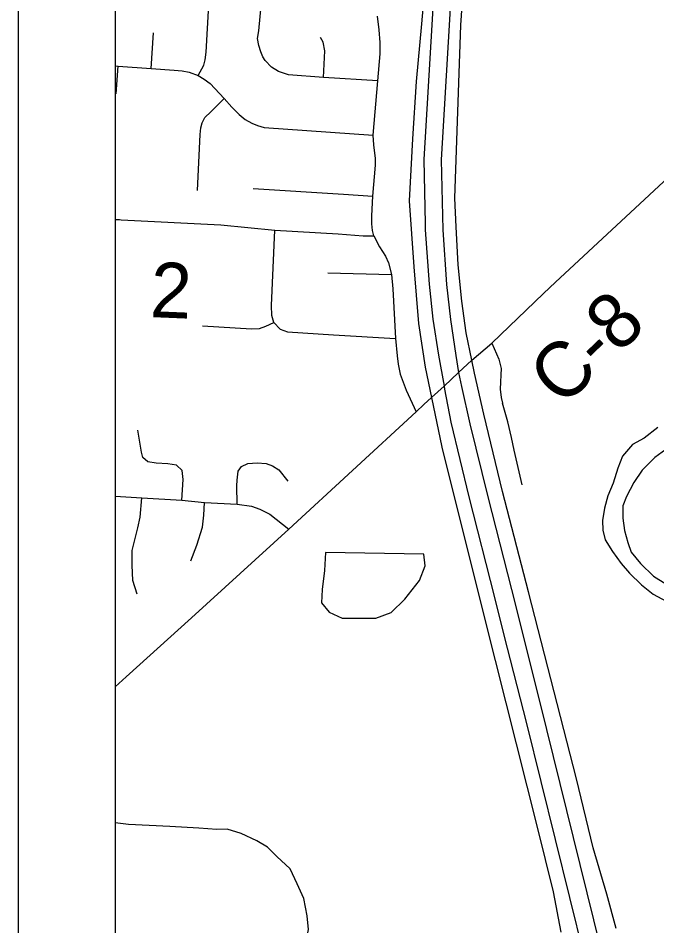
# Model space of a CAD drawing. Extents: x 208586767.6 to 208586821.4, y -134301046.9 to -134301022.9.
# Drawn here: x 208586777.928 to 208586778.586, y -134301026.633 to -134301025.698 of the extents above; entities that cross this region are included whole.
import ezdxf

# ---------------------------------------------------------------- set-up
doc = ezdxf.new("R2010")
doc.units = 0
for name, color, linetype in [('GM_X_City_Street', 7, 'Continuous'), ('GM_X_Corporation', 7, 'Continuous'), ('GM_X_County_Road', 7, 'Continuous'), ('GM_X_County_Road_Text', 7, 'Continuous'), ('GM_X_Interchange_Ramps', 7, 'Continuous'), ('GM_X_Interstate_Route', 7, 'Continuous'), ('GM_X_Major_River', 7, 'Continuous'), ('GM_X_Minor_Lake', 7, 'Continuous'), ('GM_X_Township_Road', 7, 'Continuous'), ('GM_X_Township_Road_Text', 7, 'Continuous'), ('SH_Data', 7, 'Continuous')]:
    doc.layers.add(name, color=color, linetype=linetype)

msp = doc.modelspace()

# ---------------------------------------------------------------- linework, layer by layer
at = {"layer": 'GM_X_City_Street'}
for p, q in [((208586778.06535, -134301025.74994), (208586778.06782, -134301025.71349)), ((208586778.02929, -134301025.77634), (208586778.03123, -134301025.74774)), ((208586778.24723, -134301025.96052), (208586778.31285, -134301025.96247))]:
    msp.add_line(p, q, dxfattribs=at)
for points in [[(208586778.2989, -134301025.76283), (208586778.24288, -134301025.75925), (208586778.20661, -134301025.7567), (208586778.19657, -134301025.7533), (208586778.18925, -134301025.7487), (208586778.18278, -134301025.74189), (208586778.18022, -134301025.73797), (208586778.17818, -134301025.73287), (208586778.17614, -134301025.72656), (208586778.17491, -134301025.7193), (208586778.17614, -134301025.71124), (208586778.18055, -134301025.6633)], [(208586778.11369, -134301025.75735), (208586778.1194, -134301025.74654), (208586778.12079, -134301025.74129), (208586778.12203, -134301025.73311), (208586778.1245, -134301025.68461), (208586778.12311, -134301025.67658), (208586778.12109, -134301025.67132)], [(208586778.2945, -134301025.92264), (208586778.2933, -134301025.91708), (208586778.29241, -134301025.91011), (208586778.29241, -134301025.90191), (208586778.29361, -134301025.88147), (208586778.2963, -134301025.84984), (208586778.2963, -134301025.84268), (208586778.2945, -134301025.82866), (208586778.2939, -134301025.81881), (208586778.2989, -134301025.76283), (208586778.30129, -134301025.73508), (208586778.30129, -134301025.72333), (208586778.30026, -134301025.71022), (208586778.29856, -134301025.69609)], [(208586778.24288, -134301025.75925), (208586778.24424, -134301025.73184), (208586778.24254, -134301025.72299), (208586778.23982, -134301025.71805)], [(208586778.02826, -134301025.74752), (208586778.03123, -134301025.74774), (208586778.06535, -134301025.74994), (208586778.08913, -134301025.75179), (208586778.09732, -134301025.75241), (208586778.10458, -134301025.75395), (208586778.11369, -134301025.75735), (208586778.11986, -134301025.76121), (208586778.1262, -134301025.76554), (208586778.14063, -134301025.78102), (208586778.14837, -134301025.78998), (208586778.1559, -134301025.79751), (208586778.16221, -134301025.8026), (208586778.16913, -134301025.80646), (208586778.17483, -134301025.80891), (208586778.18175, -134301025.81094), (208586778.2939, -134301025.81881)], [(208586778.11297, -134301025.87573), (208586778.11588, -134301025.81814), (208586778.11657, -134301025.8113), (208586778.11776, -134301025.80601), (208586778.12067, -134301025.80053), (208586778.12664, -134301025.7949), (208586778.14063, -134301025.78102)], [(208586778.17038, -134301025.87371), (208586778.26348, -134301025.87968), (208586778.29361, -134301025.88147)], [(208586778.19163, -134301026.01177), (208586778.18946, -134301026.00447), (208586778.18907, -134301025.9942), (208586778.19268, -134301025.91668)], [(208586778.11803, -134301026.01532), (208586778.16854, -134301026.01827), (208586778.17702, -134301026.01788), (208586778.18354, -134301026.01551), (208586778.19163, -134301026.01177)], [(208586778.19163, -134301026.01177), (208586778.19814, -134301026.01847), (208586778.20564, -134301026.02144), (208586778.2532, -134301026.02439), (208586778.31711, -134301026.02828)], [(208586778.44743, -134301026.1789), (208586778.43917, -134301026.14342), (208586778.43638, -134301026.13027), (208586778.4326, -134301026.11416), (208586778.4273, -134301026.09493)], [(208586778.09676, -134301026.19487), (208586778.09817, -134301026.17337), (208586778.09723, -134301026.16426), (208586778.09139, -134301026.15888), (208586778.08228, -134301026.15725), (208586778.07036, -134301026.15678), (208586778.06172, -134301026.15538), (208586778.05681, -134301026.15094), (208586778.05519, -134301026.14548), (208586778.05163, -134301026.12267)], [(208586778.15401, -134301026.19884), (208586778.15357, -134301026.17998), (208586778.15376, -134301026.17409), (208586778.1549, -134301026.16496), (208586778.15833, -134301026.16001), (208586778.16498, -134301026.15717), (208586778.17448, -134301026.1564), (208586778.18379, -134301026.15717), (208586778.19025, -134301026.15926), (208586778.1969, -134301026.16344), (208586778.20593, -134301026.1752)], [(208586778.02826, -134301026.19074), (208586778.05564, -134301026.19229), (208586778.09676, -134301026.19487), (208586778.12036, -134301026.1972), (208586778.15401, -134301026.19884), (208586778.16877, -134301026.20108), (208586778.17714, -134301026.20393), (208586778.1874, -134301026.20906), (208586778.20704, -134301026.2248)], [(208586778.05097, -134301026.29159), (208586778.04629, -134301026.27758), (208586778.04559, -134301026.26169), (208586778.04583, -134301026.24674), (208586778.05167, -134301026.22314), (208586778.05401, -134301026.21215), (208586778.05564, -134301026.19229)], [(208586778.10611, -134301026.25725), (208586778.11218, -134301026.24113), (208586778.11803, -134301026.22244), (208586778.11966, -134301026.21029), (208586778.12036, -134301026.1972)]]:
    msp.add_lwpolyline(points, dxfattribs=at)
at = {"layer": 'GM_X_Corporation'}
for points in [[(208586780.70516, -134301026.71709), (208586780.71564, -134301026.59783), (208586780.72517, -134301026.42102), (208586780.75163, -134301025.96027), (208586780.75793, -134301025.857), (208586780.78397, -134301025.42935), (208586780.79299, -134301025.29198), (208586780.79385, -134301025.27895), (208586780.84682, -134301024.47213), (208586780.8523, -134301024.30943), (208586780.86081, -134301024.16936), (208586780.86862, -134301024.04072), (208586778.02826, -134301024.04072), (208586778.02826, -134301026.87222)], [(208586778.02826, -134301025.18459), (208586778.02826, -134301030.32371)]]:
    msp.add_lwpolyline(points, dxfattribs=at)
at = {"layer": 'GM_X_County_Road'}
for points in [[(208586778.48186, -134301025.97017), (208586778.6751, -134301025.79061), (208586778.82536, -134301025.64512), (208586778.89868, -134301025.57327), (208586778.92318, -134301025.54795), (208586778.93255, -134301025.53677), (208586778.9411, -134301025.52543), (208586778.94685, -134301025.51639), (208586778.95162, -134301025.50817), (208586778.95606, -134301025.5006), (208586778.96214, -134301025.48926), (208586778.96807, -134301025.47479), (208586778.97201, -134301025.4618), (208586778.9748, -134301025.45358), (208586778.97503, -134301025.45268)], [(208586778.3462, -134301026.0964), (208586778.35402, -134301026.08917), (208586778.36693, -134301026.0774), (208586778.38197, -134301026.06338), (208586778.39572, -134301026.05057), (208586778.41616, -134301026.03294), (208586778.46932, -134301025.98182), (208586778.48186, -134301025.97017)], [(208586778.02826, -134301026.38702), (208586778.03951, -134301026.37671), (208586778.10675, -134301026.31605), (208586778.20704, -134301026.2248), (208586778.33839, -134301026.10364), (208586778.3462, -134301026.0964)], [(208586778.21779, -134301026.71457), (208586778.22241, -134301026.65984), (208586778.22738, -134301026.63719), (208586778.22601, -134301026.62311), (208586778.22261, -134301026.6052), (208586778.21579, -134301026.58985), (208586778.20829, -134301026.57449), (208586778.19464, -134301026.5617), (208586778.1851, -134301026.5521), (208586778.17418, -134301026.5457), (208586778.15781, -134301026.53803), (208586778.14348, -134301026.53355), (208586778.13275, -134301026.53413), (208586778.11428, -134301026.53272), (208586778.08461, -134301026.53085), (208586778.04209, -134301026.52875), (208586778.02826, -134301026.52725)]]:
    msp.add_lwpolyline(points, dxfattribs=at)
at = {"layer": 'GM_X_Interchange_Ramps'}
for points in [[(208586778.36431, -134301025.42027), (208586778.36128, -134301025.46232), (208586778.35774, -134301025.52026), (208586778.35293, -134301025.5982), (208586778.34382, -134301025.70396), (208586778.33826, -134301025.76342), (208586778.3344, -134301025.82239), (208586778.33117, -134301025.88639), (208586778.33582, -134301025.95432), (208586778.34072, -134301026.01294), (208586778.3475, -134301026.05774), (208586778.35402, -134301026.08917), (208586778.36452, -134301026.14002), (208586778.409, -134301026.31766), (208586778.46285, -134301026.53156), (208586778.4793, -134301026.59823), (208586778.48741, -134301026.6399)], [(208586778.54432, -134301026.63619), (208586778.53467, -134301026.60078), (208586778.52068, -134301026.55285), (208586778.50337, -134301026.48186), (208586778.45391, -134301026.28908), (208586778.42702, -134301026.18591), (208586778.40784, -134301026.1063), (208586778.39848, -134301026.06395), (208586778.39572, -134301026.05057), (208586778.38989, -134301026.02228), (208586778.38538, -134301025.98985), (208586778.38134, -134301025.95231), (208586778.37941, -134301025.91322), (208586778.37794, -134301025.88353), (208586778.38438, -134301025.70541), (208586778.39313, -134301025.57624), (208586778.39569, -134301025.48877)]]:
    msp.add_lwpolyline(points, dxfattribs=at)
at = {"layer": 'GM_X_Interstate_Route'}
for points in [[(208586778.39952, -134301025.26386), (208586778.39796, -134301025.28965), (208586778.39344, -134301025.36115), (208586778.38905, -134301025.43479), (208586778.38269, -134301025.53173), (208586778.36405, -134301025.84428), (208586778.36558, -134301025.91644), (208586778.36953, -134301025.97258), (208586778.37348, -134301026.00877), (208586778.37918, -134301026.04562), (208586778.38197, -134301026.06338), (208586778.38493, -134301026.07769), (208586778.39364, -134301026.11629), (208586778.41206, -134301026.1913), (208586778.44057, -134301026.30293), (208586778.47259, -134301026.43102), (208586778.54836, -134301026.73847)], [(208586778.38117, -134301025.2688), (208586778.38071, -134301025.27724), (208586778.37544, -134301025.36086), (208586778.37106, -134301025.4345), (208586778.3647, -134301025.53144), (208586778.34605, -134301025.84398), (208586778.34746, -134301025.91013)], [(208586778.34746, -134301025.91013), (208586778.34759, -134301025.91614), (208586778.35154, -134301025.97229), (208586778.35548, -134301026.00848), (208586778.36119, -134301026.04533), (208586778.36693, -134301026.0774), (208586778.36748, -134301026.08032)], [(208586778.36748, -134301026.08032), (208586778.37391, -134301026.11441), (208586778.39233, -134301026.19118), (208586778.41887, -134301026.29514), (208586778.42869, -134301026.3339)], [(208586778.42869, -134301026.3339), (208586778.45177, -134301026.42498), (208586778.52575, -134301026.72358)]]:
    msp.add_lwpolyline(points, dxfattribs=at)
at = {"layer": 'GM_X_Major_River'}
for points in [[(208586778.58724, -134301026.12), (208586778.57315, -134301026.13095), (208586778.56098, -134301026.13735), (208586778.55068, -134301026.14946), (208586778.54607, -134301026.16197), (208586778.54106, -134301026.17713), (208586778.53568, -134301026.1904), (208586778.53221, -134301026.20291), (208586778.53024, -134301026.21582), (208586778.53057, -134301026.22569), (208586778.5328, -134301026.23557), (208586778.54032, -134301026.24776), (208586778.54937, -134301026.25996), (208586778.55804, -134301026.26987), (208586778.5705, -134301026.28208), (208586778.58221, -134301026.29163), (208586778.59583, -134301026.2989)], [(208586778.59547, -134301026.14245), (208586778.58405, -134301026.15075), (208586778.57109, -134301026.16398), (208586778.5623, -134301026.17647), (208586778.55502, -134301026.19087), (208586778.55118, -134301026.20072), (208586778.55112, -134301026.21325), (208586778.55295, -134301026.22617), (208586778.5563, -134301026.23834), (208586778.55967, -134301026.24823), (208586778.56947, -134301026.26005), (208586778.58268, -134301026.27302), (208586778.59554, -134301026.28105)]]:
    msp.add_lwpolyline(points, dxfattribs=at)
at = {"layer": 'GM_X_Minor_Lake'}
for points in [[(208586778.24476, -134301026.24853), (208586778.24382, -134301026.26712), (208586778.24135, -134301026.28684), (208586778.24083, -134301026.3005), (208586778.24871, -134301026.31007), (208586778.26193, -134301026.31628), (208586778.27863, -134301026.31644), (208586778.29684, -134301026.31625), (208586778.31246, -134301026.31033), (208586778.32664, -134301026.2968), (208586778.34163, -134301026.27759), (208586778.34747, -134301026.26246), (208586778.34607, -134301026.25029)], [(208586778.34607, -134301026.25029), (208586778.24476, -134301026.24853)]]:
    msp.add_lwpolyline(points, dxfattribs=at)
at = {"layer": 'GM_X_Township_Road'}
msp.add_line((208586778.02826, -134301025.90551), (208586778.03251, -134301025.90578), dxfattribs=at)
for points in [[(208586778.03251, -134301025.90578), (208586778.03451, -134301025.9059), (208586778.13716, -134301025.91121), (208586778.19268, -134301025.91668), (208586778.2578, -134301025.92026), (208586778.28361, -134301025.92235), (208586778.2945, -134301025.92264), (208586778.30047, -134301025.93368), (208586778.30674, -134301025.94338), (208586778.30972, -134301025.95024), (208586778.31285, -134301025.96247), (208586778.31416, -134301025.977), (208586778.31711, -134301026.02828), (208586778.3187, -134301026.0462), (208586778.3196, -134301026.05483), (208586778.32164, -134301026.06503), (208586778.32807, -134301026.0816), (208586778.33839, -134301026.10364)], [(208586778.41616, -134301026.03294), (208586778.42323, -134301026.04955), (208586778.42586, -134301026.05913), (208586778.42553, -134301026.06583), (208586778.42504, -134301026.07306), (208586778.42471, -134301026.08045), (208586778.42586, -134301026.089), (208586778.4273, -134301026.09493)]]:
    msp.add_lwpolyline(points, dxfattribs=at)
at = {"layer": 'SH_Data'}
for p, q in [((208586777.92826, -134301023.94072), (208586777.92826, -134301030.94072)), ((208586778.02826, -134301024.04072), (208586778.02826, -134301030.84072))]:
    msp.add_line(p, q, dxfattribs=at)

# ---------------------------------------------------------------- texts
at = {"layer": 'GM_X_County_Road_Text'}
msp.add_text('C-8', height=0.056818, rotation=43.72953, dxfattribs=at).set_placement((208586778.48874, -134301026.10014))
at = {"layer": 'GM_X_Township_Road_Text'}
msp.add_text('2', height=0.05682, rotation=357.61453, dxfattribs=at).set_placement((208586778.06359, -134301026.00613))

doc.saveas('drawing.dxf')
